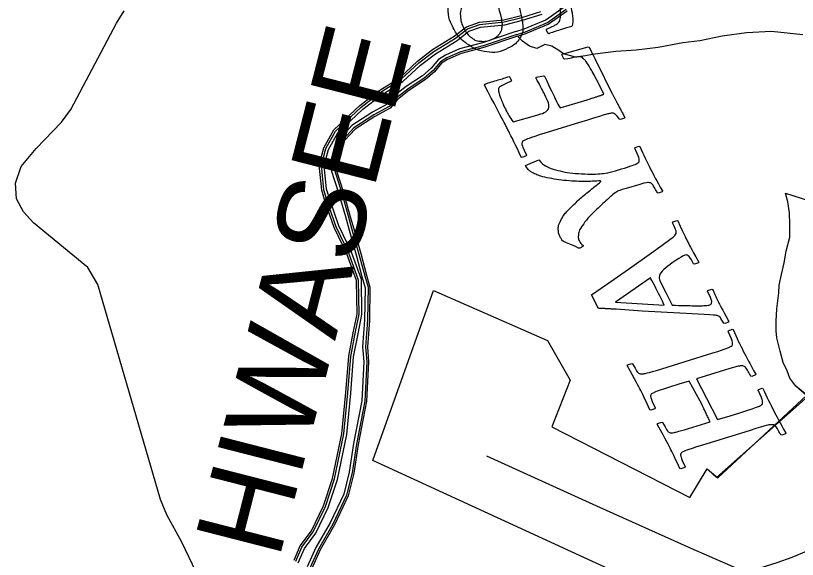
# Model space of a CAD drawing. Extents: x 558484 to 564063, y 513718 to 518374.
# Drawn here: x 559465.6 to 559524.5, y 514910.5 to 514951.5 of the extents above; entities that cross this region are included whole.
import ezdxf

# ---------------------------------------------------------------- set-up
doc = ezdxf.new("R2010")
doc.units = 0
doc.layers.add('Default', color=7, linetype='Continuous')

msp = doc.modelspace()

# ---------------------------------------------------------------- linework, layer by layer
at = {"layer": 'Default'}
for points in [[(559503.316, 514950.258), (559503.947, 514950.451), (559505.576, 514951.14), (559506.953, 514952.114)], [(559477.815, 514901.22), (559478.707, 514904.613), (559479.231, 514907.047), (559479.344, 514908.277), (559479.208, 514909.492), (559478.145, 514911.761), (559476.994, 514913.807), (559476.529, 514914.967), (559471.795, 514931.18), (559471.053, 514932.45), (559466.956, 514935.832), (559466.203, 514936.67), (559465.677, 514937.65), (559465.606, 514938.829), (559466.025, 514940.087), (559467.146, 514941.431), (559469.075, 514943.417), (559469.756, 514944.374), (559473.214, 514950.897), (559473.786, 514951.826)], [(559486.591, 514910.385), (559487.05, 514911.461), (559487.904, 514912.614), (559488.815, 514914.495), (559489.499, 514916.562), (559490.192, 514919.931), (559490.491, 514923.03), (559490.712, 514925.772), (559491.048, 514927.523), (559491.337, 514928.949), (559491.295, 514931.484), (559490.576, 514933.487), (559489.616, 514935.471), (559488.949, 514937.413), (559488.683, 514938.292), (559488.497, 514940.183), (559488.842, 514941.494), (559489.599, 514942.845), (559491.539, 514944.672), (559492.942, 514945.772), (559494.573, 514946.777), (559495.888, 514948.011), (559497.034, 514948.89), (559498.665, 514949.895), (559499.597, 514950.603), (559500.567, 514950.952), (559502.412, 514951.139), (559503.711, 514951.466)], [(559486.728, 514910.306), (559487.186, 514911.383), (559488.038, 514912.533), (559488.96, 514914.436), (559489.651, 514916.522), (559490.346, 514919.908), (559490.646, 514923.016), (559490.867, 514925.751), (559491.202, 514927.493), (559491.494, 514928.935), (559491.45, 514931.513), (559490.72, 514933.548), (559489.761, 514935.53), (559489.098, 514937.461), (559488.837, 514938.323), (559488.655, 514940.17), (559488.988, 514941.435), (559489.724, 514942.748), (559491.641, 514944.553), (559493.031, 514945.643), (559494.668, 514946.652), (559495.989, 514947.892), (559497.123, 514948.761), (559498.753, 514949.766), (559499.673, 514950.464), (559500.602, 514950.799), (559502.439, 514950.985), (559503.753, 514951.316), (559505.186, 514951.76)], [(559486.914, 514910.198), (559487.374, 514911.275), (559488.222, 514912.421), (559489.159, 514914.355), (559489.858, 514916.466), (559490.558, 514919.876), (559490.86, 514922.997), (559491.079, 514925.722), (559491.412, 514927.451), (559491.708, 514928.915), (559491.664, 514931.552), (559490.918, 514933.631), (559489.959, 514935.612), (559489.302, 514937.527), (559489.048, 514938.365), (559488.872, 514940.153), (559489.188, 514941.354), (559489.895, 514942.614), (559491.781, 514944.39), (559493.154, 514945.467), (559494.799, 514946.481), (559496.128, 514947.729), (559497.244, 514948.585), (559498.874, 514949.59), (559499.776, 514950.274), (559500.649, 514950.589), (559502.476, 514950.774), (559503.811, 514951.109), (559505.282, 514951.565)], [(559503.389, 514950.043), (559504.025, 514950.237), (559505.687, 514950.94), (559507.094, 514951.935)], [(559503.433, 514949.915), (559504.071, 514950.109), (559505.753, 514950.821), (559507.178, 514951.829)], [(559505.808, 514950.093), (559505.732, 514950.126), (559505.607, 514950.372), (559505.627, 514950.435), (559506.218, 514950.723)], [(559507.557, 514950.68), (559507.505, 514950.627)], [(559503.316, 514950.258), (559500.79, 514949.398), (559499.059, 514948.94), (559497.996, 514948.473), (559497.469, 514948.146), (559496.918, 514947.484), (559496.267, 514946.922), (559495.036, 514946.101), (559494.132, 514945.407), (559493.601, 514944.775), (559492.5, 514944.166), (559490.954, 514943.177), (559490.118, 514942.252), (559489.606, 514941.494), (559489.376, 514939.874), (559489.972, 514938.006), (559490.459, 514936.297), (559490.789, 514935.097), (559491.264, 514933.409), (559491.711, 514931.781), (559491.947, 514930.938), (559491.91, 514928.491), (559491.755, 514926.487), (559491.846, 514925.353), (559491.7, 514922.416), (559491.068, 514919.183), (559490.75, 514917.029), (559490.335, 514915.378), (559489.306, 514913.218), (559488.233, 514911.336), (559487.576, 514909.885)], [(559503.389, 514950.043), (559500.856, 514949.18), (559499.135, 514948.725), (559498.102, 514948.271), (559497.62, 514947.972), (559497.08, 514947.324), (559496.404, 514946.741), (559495.169, 514945.916), (559494.29, 514945.242), (559493.748, 514944.597), (559492.616, 514943.971), (559491.102, 514943.002), (559490.298, 514942.112), (559489.824, 514941.41), (559489.608, 514939.894), (559490.19, 514938.071), (559490.678, 514936.358), (559491.008, 514935.158), (559491.484, 514933.47), (559491.93, 514931.842), (559492.174, 514930.968), (559492.138, 514928.481), (559491.983, 514926.487), (559492.074, 514925.356), (559491.926, 514922.389), (559491.292, 514919.145), (559490.973, 514916.985), (559490.551, 514915.3), (559489.508, 514913.112), (559488.436, 514911.232), (559487.776, 514909.777)], [(559503.433, 514949.915), (559500.895, 514949.051), (559499.18, 514948.596), (559498.165, 514948.151), (559497.71, 514947.868), (559497.177, 514947.229), (559496.487, 514946.633), (559495.248, 514945.806), (559494.384, 514945.143), (559493.835, 514944.49), (559492.686, 514943.855), (559491.19, 514942.898), (559490.405, 514942.028), (559489.954, 514941.36), (559489.747, 514939.905), (559490.319, 514938.111), (559490.808, 514936.395), (559491.139, 514935.194), (559491.614, 514933.506), (559492.061, 514931.878), (559492.31, 514930.985), (559492.273, 514928.474), (559492.119, 514926.487), (559492.21, 514925.359), (559492.061, 514922.372), (559491.425, 514919.122), (559491.106, 514916.958), (559490.679, 514915.254), (559489.628, 514913.05), (559488.556, 514911.171), (559487.896, 514909.713)], [(559524.939, 514950.017), (559522.569, 514950.265), (559520.701, 514950.154), (559518.854, 514949.916), (559517.169, 514949.545), (559515.901, 514949.392), (559514.035, 514949.044), (559512.373, 514948.853), (559510.842, 514948.755), (559509.869, 514948.631), (559509.093, 514948.527), (559508.556, 514948.425), (559507.809, 514948.334), (559506.911, 514948.584), (559506.558, 514948.837), (559506.012, 514949.141), (559505.501, 514949.29), (559504.884, 514948.984), (559504.331, 514949.148), (559503.817, 514949.535), (559503.433, 514949.915)], [(559506.992, 514948.167), (559506.929, 514948.188), (559506.772, 514948.496), (559506.795, 514948.554), (559508.757, 514949.112), (559508.833, 514949.078)], [(559509.401, 514947.925), (559510.554, 514945.608)], [(559502.774, 514946.869), (559502.84, 514946.843), (559502.978, 514946.571), (559502.958, 514946.508)], [(559504.811, 514946.761), (559504.858, 514946.824), (559505.387, 514946.922), (559505.467, 514946.883)], [(559500.95, 514946.21), (559500.986, 514946.295)], [(559509.946, 514945.536), (559509.504, 514946.404)], [(559506.639, 514944.491), (559508.679, 514945.114)], [(559503.095, 514943.444), (559504.892, 514943.95)], [(559511.52, 514943.789), (559511.502, 514943.734)], [(559508.035, 514943.378), (559505.498, 514942.593)], [(559511.502, 514943.734), (559511.206, 514943.629), (559511.132, 514943.657)], [(559512.53, 514940.886), (559512.272, 514941.459), (559512.295, 514941.517), (559512.572, 514941.619), (559512.643, 514941.596)], [(559504.106, 514940.929), (559504.083, 514940.871), (559503.774, 514940.767), (559503.708, 514940.793)], [(559504.035, 514940.15), (559505.04, 514940.582)], [(559512.656, 514938.725), (559511.63, 514938.426)], [(559513.733, 514908.143), (559492.521, 514917.897), (559497.095, 514930.733), (559505.702, 514926.956), (559507.415, 514923.972), (559506.016, 514920.452), (559516.433, 514915.128), (559517.719, 514917.287), (559518.535, 514916.597), (559525.209, 514922.817), (559524.411, 514923.516), (559523.972, 514924.107), (559523.75, 514924.67), (559523.467, 514925.306), (559523.23, 514926.162), (559522.99, 514927.154), (559522.922, 514927.686), (559522.93, 514928.426), (559522.974, 514929.357), (559523.13, 514930.551), (559523.151, 514931.135), (559523.332, 514931.94), (559523.544, 514932.809), (559523.69, 514933.685), (559523.948, 514934.749), (559523.971, 514935.721), (559523.93, 514936.59), (559523.821, 514937.415), (559523.632, 514938.068), (559530.462, 514935.879)], [(559513.733, 514908.143), (559492.521, 514917.897), (559497.095, 514930.733), (559505.702, 514926.956), (559507.415, 514923.972), (559506.016, 514920.452), (559516.433, 514915.128), (559517.719, 514917.287), (559518.435, 514916.628), (559525.333, 514922.753), (559524.411, 514923.516), (559523.972, 514924.107), (559523.75, 514924.67), (559523.467, 514925.306), (559523.23, 514926.162), (559522.99, 514927.154), (559522.922, 514927.686), (559522.93, 514928.426), (559522.974, 514929.357), (559523.13, 514930.551), (559523.151, 514931.135), (559523.332, 514931.94), (559523.544, 514932.809), (559523.69, 514933.685), (559523.948, 514934.749), (559523.971, 514935.721), (559523.93, 514936.59), (559523.821, 514937.415), (559523.632, 514938.068), (559530.462, 514935.879)], [(559513.733, 514908.143), (559492.521, 514917.897), (559497.095, 514930.733), (559505.702, 514926.956), (559507.415, 514923.972), (559506.016, 514920.452), (559516.433, 514915.128), (559517.719, 514917.287), (559518.535, 514916.597), (559525.209, 514922.817), (559524.411, 514923.516), (559523.972, 514924.107), (559523.75, 514924.67), (559523.467, 514925.306), (559523.23, 514926.162), (559522.99, 514927.154), (559522.922, 514927.686), (559522.93, 514928.426), (559522.974, 514929.357), (559523.13, 514930.551), (559523.151, 514931.135), (559523.332, 514931.94), (559523.544, 514932.809), (559523.69, 514933.685), (559523.948, 514934.749), (559523.971, 514935.721), (559523.93, 514936.59), (559523.821, 514937.415), (559523.632, 514938.068), (559530.462, 514935.879)], [(559514.355, 514938.233), (559514.332, 514938.175), (559514.057, 514938.068), (559513.983, 514938.096)], [(559515.125, 514935.84), (559515.154, 514935.901), (559515.437, 514936.005), (559515.51, 514935.977)], [(559509.53, 514929.37), (559509.011, 514930.389), (559510.46, 514931.397), (559512.061, 514932.522), (559513.369, 514933.445), (559514.343, 514934.144), (559514.922, 514934.571)], [(559508.388, 514934.109), (559508.365, 514934.038), (559508.13, 514933.918), (559508.035, 514933.922)], [(559517.092, 514932.871), (559517.066, 514932.805), (559516.778, 514932.711), (559516.704, 514932.739)], [(559513.453, 514931.689), (559510.831, 514929.841), (559514.499, 514929.634)], [(559514.211, 514931.364), (559514.623, 514930.567), (559515.103, 514929.626)], [(559517.759, 514930.668), (559517.787, 514930.729), (559518.078, 514930.831), (559518.146, 514930.8)], [(559517.493, 514928.913), (559516.141, 514928.995), (559512.841, 514929.179), (559510.859, 514929.309)], [(559519.371, 514928.394), (559519.343, 514928.334), (559519.052, 514928.232), (559518.983, 514928.263)], [(559519.553, 514927.093), (559519.307, 514927.64), (559519.33, 514927.698), (559519.608, 514927.8), (559519.679, 514927.777)], [(559513.906, 514924.706), (559518.167, 514926.026)], [(559511.707, 514925.081), (559511.733, 514925.134), (559512.044, 514925.233), (559512.11, 514925.207)], [(559519.037, 514924.717), (559516.934, 514924.075), (559517.677, 514922.602), (559518.502, 514920.994)], [(559521.391, 514924.414), (559521.368, 514924.356), (559521.09, 514924.255), (559521.019, 514924.278)], [(559517.199, 514922.392), (559516.384, 514923.9)], [(559521.813, 514922.654), (559521.565, 514923.206), (559521.588, 514923.263), (559521.865, 514923.365), (559521.937, 514923.342)], [(559513.595, 514922.355), (559513.809, 514921.871), (559513.786, 514921.813), (559513.477, 514921.708), (559513.411, 514921.734)], [(559516.316, 514920.322), (559517.953, 514920.82)], [(559513.965, 514920.647), (559513.991, 514920.699), (559514.302, 514920.799), (559514.368, 514920.773)], [(559520.965, 514920.18), (559517.943, 514919.248)], [(559523.648, 514919.98), (559523.625, 514919.922), (559523.351, 514919.815), (559523.277, 514919.843)], [(559520.667, 514909.463), (559516.534, 514911.276), (559509.409, 514914.472), (559501.127, 514918.243)], [(559515.853, 514917.92), (559516.067, 514917.436), (559516.044, 514917.378), (559515.735, 514917.274), (559515.669, 514917.3)], [(559527.73, 514913.893), (559527.025, 514912.605), (559526.681, 514912.163), (559526.336, 514911.81), (559525.955, 514911.492), (559525.183, 514911.055), (559524.105, 514910.587), (559522.979, 514910.19), (559520.667, 514909.463)]]:
    msp.add_lwpolyline(points, dxfattribs=at)
for points, degree in [([(559499.282, 514952.189), (559499.098, 514951.865), (559499.134, 514951.399), (559499.17, 514950.934), (559499.394, 514950.495), (559499.61, 514950.071), (559499.955, 514949.799), (559500.301, 514949.528), (559500.75, 514949.519), (559501.199, 514949.51), (559501.617, 514949.723), (559501.941, 514949.889), (559502.092, 514950.11), (559502.243, 514950.332), (559502.272, 514950.577), (559502.302, 514950.823), (559502.265, 514951.071), (559502.227, 514951.318), (559502.036, 514951.978), (559501.869, 514952.565), (559501.834, 514952.893), (559501.799, 514953.221), (559501.886, 514953.502), (559501.973, 514953.783), (559502.212, 514954.046), (559502.45, 514954.309), (559502.811, 514954.493), (559503.517, 514954.852), (559504.393, 514954.748), (559505.269, 514954.645), (559506, 514954.158), (559506.732, 514953.671), (559507.166, 514952.819), (559507.435, 514952.291), (559507.538, 514951.714), (559507.64, 514951.137), (559507.557, 514950.68)], 3), ([(559506.218, 514950.723), (559506.291, 514950.76), (559506.511, 514950.885), (559506.682, 514951.157), (559506.674, 514951.742), (559506.666, 514952.327), (559506.397, 514952.855), (559505.987, 514953.66), (559505.334, 514953.832), (559504.68, 514954.003), (559504.11, 514953.712), (559503.854, 514953.582), (559503.694, 514953.392), (559503.534, 514953.202), (559503.485, 514953.019), (559503.437, 514952.836), (559503.459, 514952.637), (559503.482, 514952.438), (559503.579, 514952.039), (559503.806, 514951.088), (559503.832, 514950.624), (559503.858, 514950.16), (559503.591, 514949.734), (559503.323, 514949.308), (559502.738, 514949.01), (559501.943, 514948.605), (559501.115, 514948.73), (559500.288, 514948.856), (559499.625, 514949.335), (559498.963, 514949.814), (559498.582, 514950.562), (559498.106, 514951.498), (559498.228, 514952.41)], 3), ([(559507.505, 514950.627), (559507.319, 514950.592), (559506.65, 514950.38), (559505.981, 514950.167), (559505.808, 514950.093)], 3), ([(559508.833, 514949.078), (559509.244, 514948.234), (559509.401, 514947.925)], 2), ([(559509.504, 514946.404), (559509.168, 514947.063), (559508.888, 514947.536), (559508.608, 514948.009), (559508.465, 514948.16), (559508.322, 514948.311), (559508.175, 514948.341), (559508.028, 514948.372), (559507.511, 514948.26), (559507.383, 514948.228), (559506.992, 514948.167)], 3), ([(559500.986, 514946.295), (559501.117, 514946.348), (559501.952, 514946.595), (559502.397, 514946.73), (559502.774, 514946.869)], 3), ([(559504.892, 514943.95), (559505.295, 514944.064), (559506.063, 514944.303), (559505.508, 514945.456), (559505.354, 514945.759), (559505.114, 514946.23), (559504.811, 514946.761)], 3), ([(559505.467, 514946.883), (559505.941, 514945.9), (559506.41, 514944.914), (559506.503, 514944.731), (559506.639, 514944.491)], 3), ([(559503.708, 514940.793), (559503.321, 514941.643), (559502.605, 514943.049), (559502.477, 514943.3), (559500.95, 514946.21)], 3), ([(559502.958, 514946.508), (559502.338, 514946.213), (559502.217, 514946.151), (559502.061, 514946.071), (559502.022, 514946.006), (559501.983, 514945.94), (559502.005, 514945.767), (559502.027, 514945.593), (559502.195, 514945.162), (559502.362, 514944.73), (559502.548, 514944.364), (559502.841, 514943.789), (559503.095, 514943.444)], 3), ([(559510.554, 514945.608), (559510.959, 514944.813), (559511.52, 514943.789)], 2), ([(559508.679, 514945.114), (559509.564, 514945.381), (559509.946, 514945.536)], 2), ([(559511.132, 514943.657), (559510.825, 514944.015), (559510.731, 514944.072), (559510.683, 514944.1), (559510.62, 514944.108), (559510.557, 514944.115), (559510.307, 514944.057), (559510.057, 514943.998), (559508.035, 514943.378)], 3), ([(559505.498, 514942.593), (559504.244, 514942.198), (559503.935, 514942.041), (559503.804, 514941.974), (559503.775, 514941.877), (559503.745, 514941.78), (559503.783, 514941.68), (559503.82, 514941.581), (559504.106, 514940.929)], 3), ([(559512.643, 514941.596), (559512.915, 514940.97), (559513.483, 514939.856), (559513.898, 514939.041), (559514.355, 514938.233)], 3), ([(559505.04, 514940.582), (559505.252, 514940.308), (559505.544, 514940.135), (559505.929, 514939.909), (559506.638, 514939.74), (559507.346, 514939.57), (559508.269, 514939.53), (559509.192, 514939.489), (559509.778, 514939.547), (559510.364, 514939.605), (559511.275, 514939.892), (559512.186, 514940.178), (559512.427, 514940.3), (559512.599, 514940.388), (559512.609, 514940.538), (559512.618, 514940.687), (559512.53, 514940.886)], 3), ([(559508.035, 514933.922), (559507.688, 514934.101), (559507.372, 514934.23), (559506.877, 514934.426), (559506.845, 514934.449), (559506.699, 514934.658), (559506.654, 514934.747), (559506.524, 514935.003), (559506.507, 514935.314), (559506.49, 514935.625), (559506.73, 514936.073), (559506.969, 514936.521), (559507.608, 514937.142), (559508.246, 514937.763), (559509.045, 514938.394), (559509.7, 514938.918), (559509.814, 514939.016), (559509.028, 514938.958), (559508.567, 514938.951), (559508.106, 514938.943), (559507.321, 514938.998), (559506.536, 514939.053), (559505.84, 514939.198), (559505.143, 514939.344), (559504.81, 514939.494), (559504.477, 514939.644), (559504.311, 514939.796), (559504.144, 514939.949), (559504.035, 514940.15)], 3), ([(559513.983, 514938.096), (559513.944, 514938.162), (559513.845, 514938.329), (559513.627, 514938.718), (559513.544, 514938.785), (559513.461, 514938.851), (559513.314, 514938.862), (559513.167, 514938.873), (559512.656, 514938.725)], 3), ([(559511.63, 514938.426), (559511.119, 514938.278), (559510.999, 514938.216), (559510.701, 514938.065), (559509.751, 514937.169), (559508.8, 514936.274), (559508.426, 514935.767), (559508.052, 514935.261), (559508.025, 514934.958), (559507.999, 514934.654), (559508.132, 514934.393), (559508.212, 514934.236), (559508.388, 514934.109)], 3), ([(559514.922, 514934.571), (559515.322, 514934.847), (559515.381, 514935.029), (559515.44, 514935.21), (559515.125, 514935.84)], 3), ([(559515.51, 514935.977), (559516.07, 514934.774), (559516.273, 514934.376), (559516.448, 514934.031), (559517.092, 514932.871)], 3), ([(559516.704, 514932.739), (559516.446, 514933.247), (559516.296, 514933.348), (559516.145, 514933.449), (559515.973, 514933.361), (559515.607, 514933.175), (559513.899, 514931.989), (559514.136, 514931.511), (559514.211, 514931.364)], 3), ([(559514.499, 514929.634), (559514.376, 514929.888), (559514.35, 514929.94), (559513.522, 514931.567), (559513.453, 514931.689)], 3), ([(559515.103, 514929.626), (559515.793, 514929.589), (559516.635, 514929.583), (559517.478, 514929.577), (559517.692, 514929.604), (559517.905, 514929.63), (559517.968, 514929.662), (559518.062, 514929.71), (559518.072, 514929.853), (559518.081, 514929.996), (559517.759, 514930.668)], 3), ([(559518.146, 514930.8), (559518.149, 514930.795), (559518.32, 514930.407), (559518.554, 514929.895), (559518.687, 514929.633), (559518.765, 514929.482), (559519.371, 514928.394)], 3), ([(559510.859, 514929.309), (559509.997, 514929.371), (559509.53, 514929.37)], 2), ([(559518.983, 514928.263), (559518.744, 514928.655), (559518.701, 514928.708), (559518.657, 514928.762), (559518.578, 514928.8), (559518.499, 514928.839), (559518.376, 514928.855), (559518.252, 514928.872), (559517.493, 514928.913)], 3), ([(559519.679, 514927.777), (559519.951, 514927.151), (559520.46, 514926.153), (559520.944, 514925.201), (559521.391, 514924.414)], 3), ([(559518.167, 514926.026), (559519.232, 514926.364), (559519.468, 514926.484), (559519.63, 514926.566), (559519.646, 514926.71), (559519.662, 514926.853), (559519.553, 514927.093)], 3), ([(559513.411, 514921.734), (559513.139, 514922.36), (559512.699, 514923.222), (559512.356, 514923.897), (559511.707, 514925.081)], 3), ([(559512.11, 514925.207), (559512.432, 514924.627), (559512.494, 514924.557), (559512.556, 514924.486), (559512.634, 514924.457), (559512.712, 514924.427), (559512.827, 514924.433), (559513.016, 514924.45), (559513.906, 514924.706)], 3), ([(559521.019, 514924.278), (559520.99, 514924.322), (559520.881, 514924.51), (559520.644, 514924.936), (559520.54, 514924.998), (559520.436, 514925.061), (559520.23, 514925.038), (559520.024, 514925.016), (559519.037, 514924.717)], 3), ([(559516.384, 514923.9), (559513.975, 514923.161), (559513.63, 514922.985), (559513.531, 514922.935), (559513.495, 514922.863), (559513.458, 514922.792), (559513.476, 514922.693), (559513.494, 514922.593), (559513.595, 514922.355)], 3), ([(559521.937, 514923.342), (559522.246, 514922.644), (559522.717, 514921.718), (559523.202, 514920.766), (559523.648, 514919.98)], 3), ([(559518.502, 514920.994), (559521.365, 514921.866), (559521.725, 514922.049), (559521.888, 514922.132), (559521.902, 514922.278), (559521.917, 514922.423), (559521.813, 514922.654)], 3), ([(559517.953, 514920.82), (559517.462, 514921.874), (559517.199, 514922.392)], 2), ([(559515.669, 514917.3), (559515.386, 514917.946), (559514.957, 514918.788), (559514.678, 514919.337), (559513.965, 514920.647)], 3), ([(559514.368, 514920.773), (559514.682, 514920.208), (559514.743, 514920.134), (559514.804, 514920.059), (559514.898, 514920.022), (559514.993, 514919.985), (559515.211, 514920.017), (559515.428, 514920.048), (559516.316, 514920.322)], 3), ([(559523.277, 514919.843), (559523.248, 514919.887), (559523.139, 514920.076), (559522.899, 514920.507), (559522.798, 514920.564), (559522.696, 514920.621), (559522.492, 514920.602), (559522.287, 514920.584), (559520.965, 514920.18)], 3), ([(559517.943, 514919.248), (559516.236, 514918.721), (559515.896, 514918.548), (559515.791, 514918.495), (559515.754, 514918.426), (559515.716, 514918.358), (559515.734, 514918.258), (559515.752, 514918.158), (559515.853, 514917.92)], 3)]:
    msp.add_open_spline(points, degree=degree, dxfattribs=at)

# ---------------------------------------------------------------- texts
msp.add_text('HIWASEE', height=6.5625, rotation=75.62, dxfattribs=at).set_placement((559485.443, 514910.366))

doc.saveas('drawing.dxf')
